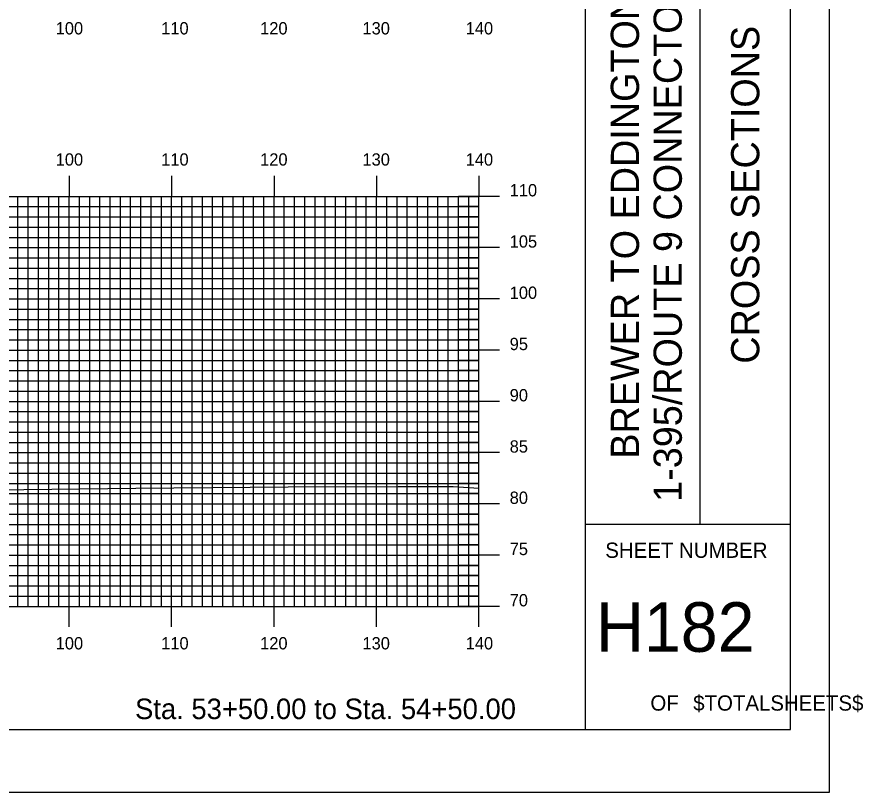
# Model space of a CAD drawing. Extents: x 1756282 to 1756625, y 442591 to 442811.
# Drawn here: x 1756542.5 to 1756625.1, y 442590.5 to 442666.2 of the extents above; entities that cross this region are included whole.
import ezdxf

# ---------------------------------------------------------------- set-up
doc = ezdxf.new("R2010")
doc.units = 0
for name, color, linetype in [('BORDER', 7, 'Continuous'), ('H_V ANNOTATION', 7, 'Continuous'), ('MAJOR', 7, 'Continuous'), ('MINOR', 7, 'Continuous'), ('PLOT BOUNDARY', 7, 'Continuous'), ('S_Roadway_Centerline', 7, 'Continuous')]:
    doc.layers.add(name, color=color, linetype=linetype)

msp = doc.modelspace()

# ---------------------------------------------------------------- linework, layer by layer
at = {"layer": 'BORDER'}
for p, q in [((1756597.97, 442596.665), (1756597.97, 442806.665)), ((1756609.152, 442616.671), (1756609.152, 442686.671)), ((1756597.97, 442616.671), (1756617.97, 442616.671))]:
    msp.add_line(p, q, dxfattribs=at)
msp.add_lwpolyline([(1756297.97, 442596.665), (1756617.97, 442596.665), (1756617.97, 442806.665), (1756297.97, 442806.665)], close=True, dxfattribs=at)
at = {"layer": 'MAJOR'}
for p, q in [((1756547.57, 442650.669), (1756547.57, 442648.665)), ((1756557.57, 442650.669), (1756557.57, 442648.665)), ((1756567.57, 442650.669), (1756567.57, 442648.665)), ((1756577.57, 442650.669), (1756577.57, 442648.665)), ((1756587.57, 442650.669), (1756587.57, 442648.665)), ((1756307.57, 442648.665), (1756587.57, 442648.665)), ((1756307.57, 442648.665), (1756587.57, 442648.665)), ((1756547.57, 442608.665), (1756547.57, 442648.665)), ((1756557.57, 442608.665), (1756557.57, 442648.665)), ((1756567.57, 442608.665), (1756567.57, 442648.665)), ((1756577.57, 442608.665), (1756577.57, 442648.665)), ((1756589.574, 442648.665), (1756585.566, 442648.665)), ((1756587.57, 442608.665), (1756587.57, 442648.665)), ((1756587.57, 442608.665), (1756587.57, 442648.665)), ((1756307.57, 442643.665), (1756587.57, 442643.665)), ((1756589.574, 442643.665), (1756585.566, 442643.665)), ((1756307.57, 442638.665), (1756587.57, 442638.665)), ((1756589.574, 442638.665), (1756585.566, 442638.665)), ((1756307.57, 442633.665), (1756587.57, 442633.665)), ((1756589.574, 442633.665), (1756585.566, 442633.665)), ((1756307.57, 442628.665), (1756587.57, 442628.665)), ((1756589.574, 442628.665), (1756585.566, 442628.665)), ((1756307.57, 442623.665), (1756587.57, 442623.665)), ((1756589.574, 442623.665), (1756585.566, 442623.665)), ((1756307.57, 442618.665), (1756587.57, 442618.665)), ((1756589.574, 442618.665), (1756585.566, 442618.665)), ((1756307.57, 442613.665), (1756587.57, 442613.665)), ((1756589.574, 442613.665), (1756585.566, 442613.665)), ((1756307.57, 442608.665), (1756587.57, 442608.665)), ((1756307.57, 442608.665), (1756587.57, 442608.665)), ((1756547.57, 442606.661), (1756547.57, 442608.665)), ((1756557.57, 442606.661), (1756557.57, 442608.665)), ((1756567.57, 442606.661), (1756567.57, 442608.665)), ((1756577.57, 442606.661), (1756577.57, 442608.665)), ((1756589.574, 442608.665), (1756585.566, 442608.665)), ((1756587.57, 442606.661), (1756587.57, 442608.665))]:
    msp.add_line(p, q, dxfattribs=at)
at = {"layer": 'MINOR'}
for p, q in [((1756542.57, 442608.665), (1756542.57, 442648.665)), ((1756543.57, 442608.665), (1756543.57, 442648.665)), ((1756544.57, 442608.665), (1756544.57, 442648.665)), ((1756545.57, 442608.665), (1756545.57, 442648.665)), ((1756546.57, 442608.665), (1756546.57, 442648.665)), ((1756548.57, 442608.665), (1756548.57, 442648.665)), ((1756549.57, 442608.665), (1756549.57, 442648.665)), ((1756550.57, 442608.665), (1756550.57, 442648.665)), ((1756551.57, 442608.665), (1756551.57, 442648.665)), ((1756552.57, 442608.665), (1756552.57, 442648.665)), ((1756553.57, 442608.665), (1756553.57, 442648.665)), ((1756554.57, 442608.665), (1756554.57, 442648.665)), ((1756555.57, 442608.665), (1756555.57, 442648.665)), ((1756556.57, 442608.665), (1756556.57, 442648.665)), ((1756558.57, 442608.665), (1756558.57, 442648.665)), ((1756559.57, 442608.665), (1756559.57, 442648.665)), ((1756560.57, 442608.665), (1756560.57, 442648.665)), ((1756561.57, 442608.665), (1756561.57, 442648.665)), ((1756562.57, 442608.665), (1756562.57, 442648.665)), ((1756563.57, 442608.665), (1756563.57, 442648.665)), ((1756564.57, 442608.665), (1756564.57, 442648.665)), ((1756565.57, 442608.665), (1756565.57, 442648.665)), ((1756566.57, 442608.665), (1756566.57, 442648.665)), ((1756568.57, 442608.665), (1756568.57, 442648.665)), ((1756569.57, 442608.665), (1756569.57, 442648.665)), ((1756570.57, 442608.665), (1756570.57, 442648.665)), ((1756571.57, 442608.665), (1756571.57, 442648.665)), ((1756572.57, 442608.665), (1756572.57, 442648.665)), ((1756573.57, 442608.665), (1756573.57, 442648.665)), ((1756574.57, 442608.665), (1756574.57, 442648.665)), ((1756575.57, 442608.665), (1756575.57, 442648.665)), ((1756576.57, 442608.665), (1756576.57, 442648.665)), ((1756578.57, 442608.665), (1756578.57, 442648.665)), ((1756579.57, 442608.665), (1756579.57, 442648.665)), ((1756580.57, 442608.665), (1756580.57, 442648.665)), ((1756581.57, 442608.665), (1756581.57, 442648.665)), ((1756582.57, 442608.665), (1756582.57, 442648.665)), ((1756583.57, 442608.665), (1756583.57, 442648.665)), ((1756584.57, 442608.665), (1756584.57, 442648.665)), ((1756585.57, 442608.665), (1756585.57, 442648.665)), ((1756586.57, 442608.665), (1756586.57, 442648.665)), ((1756307.57, 442647.665), (1756587.57, 442647.665)), ((1756587.57, 442647.665), (1756585.566, 442647.665)), ((1756307.57, 442646.665), (1756587.57, 442646.665)), ((1756587.57, 442646.665), (1756585.566, 442646.665)), ((1756307.57, 442645.665), (1756587.57, 442645.665)), ((1756587.57, 442645.665), (1756585.566, 442645.665)), ((1756307.57, 442644.665), (1756587.57, 442644.665)), ((1756587.57, 442644.665), (1756585.566, 442644.665)), ((1756307.57, 442642.665), (1756587.57, 442642.665)), ((1756587.57, 442642.665), (1756585.566, 442642.665)), ((1756307.57, 442641.665), (1756587.57, 442641.665)), ((1756587.57, 442641.665), (1756585.566, 442641.665)), ((1756307.57, 442640.665), (1756587.57, 442640.665)), ((1756587.57, 442640.665), (1756585.566, 442640.665)), ((1756307.57, 442639.665), (1756587.57, 442639.665)), ((1756587.57, 442639.665), (1756585.566, 442639.665)), ((1756307.57, 442637.665), (1756587.57, 442637.665)), ((1756587.57, 442637.665), (1756585.566, 442637.665)), ((1756307.57, 442636.665), (1756587.57, 442636.665)), ((1756587.57, 442636.665), (1756585.566, 442636.665)), ((1756307.57, 442635.665), (1756587.57, 442635.665)), ((1756587.57, 442635.665), (1756585.566, 442635.665)), ((1756307.57, 442634.665), (1756587.57, 442634.665)), ((1756587.57, 442634.665), (1756585.566, 442634.665)), ((1756307.57, 442632.665), (1756587.57, 442632.665)), ((1756587.57, 442632.665), (1756585.566, 442632.665)), ((1756307.57, 442631.665), (1756587.57, 442631.665)), ((1756587.57, 442631.665), (1756585.566, 442631.665)), ((1756307.57, 442630.665), (1756587.57, 442630.665)), ((1756587.57, 442630.665), (1756585.566, 442630.665)), ((1756307.57, 442629.665), (1756587.57, 442629.665)), ((1756587.57, 442629.665), (1756585.566, 442629.665)), ((1756307.57, 442627.665), (1756587.57, 442627.665)), ((1756587.57, 442627.665), (1756585.566, 442627.665)), ((1756307.57, 442626.665), (1756587.57, 442626.665)), ((1756587.57, 442626.665), (1756585.566, 442626.665)), ((1756307.57, 442625.665), (1756587.57, 442625.665)), ((1756587.57, 442625.665), (1756585.566, 442625.665)), ((1756307.57, 442624.665), (1756587.57, 442624.665)), ((1756587.57, 442624.665), (1756585.566, 442624.665)), ((1756307.57, 442622.665), (1756587.57, 442622.665)), ((1756587.57, 442622.665), (1756585.566, 442622.665)), ((1756307.57, 442621.665), (1756587.57, 442621.665)), ((1756587.57, 442621.665), (1756585.566, 442621.665)), ((1756307.57, 442620.665), (1756587.57, 442620.665)), ((1756587.57, 442620.665), (1756585.566, 442620.665)), ((1756307.57, 442619.665), (1756587.57, 442619.665)), ((1756587.57, 442619.665), (1756585.566, 442619.665)), ((1756307.57, 442617.665), (1756587.57, 442617.665)), ((1756587.57, 442617.665), (1756585.566, 442617.665)), ((1756307.57, 442616.665), (1756587.57, 442616.665)), ((1756587.57, 442616.665), (1756585.566, 442616.665)), ((1756307.57, 442615.665), (1756587.57, 442615.665)), ((1756587.57, 442615.665), (1756585.566, 442615.665)), ((1756307.57, 442614.665), (1756587.57, 442614.665)), ((1756587.57, 442614.665), (1756585.566, 442614.665)), ((1756307.57, 442612.665), (1756587.57, 442612.665)), ((1756587.57, 442612.665), (1756585.566, 442612.665)), ((1756307.57, 442611.665), (1756587.57, 442611.665)), ((1756587.57, 442611.665), (1756585.566, 442611.665)), ((1756307.57, 442610.665), (1756587.57, 442610.665)), ((1756587.57, 442610.665), (1756585.566, 442610.665)), ((1756307.57, 442609.665), (1756587.57, 442609.665)), ((1756587.57, 442609.665), (1756585.566, 442609.665))]:
    msp.add_line(p, q, dxfattribs=at)
at = {"layer": 'PLOT BOUNDARY'}
msp.add_lwpolyline([(1756281.783, 442590.547), (1756621.783, 442590.547), (1756621.783, 442810.547), (1756281.783, 442810.547)], close=True, dxfattribs=at)
at = {"layer": 'S_Roadway_Centerline'}
msp.add_lwpolyline([(1756307.57, 442618.076), (1756314.44, 442618.161), (1756314.669, 442617.912), (1756326.373, 442617.543), (1756331.277, 442617.486), (1756351.519, 442618.675), (1756360.562, 442619.108), (1756369.53, 442619.264), (1756401.492, 442619.32), (1756415.224, 442619.955), (1756421.47, 442620.052), (1756445.661, 442619.395), (1756471.396, 442619.404), (1756485.635, 442619.606), (1756486.605, 442619.72), (1756492.846, 442619.489), (1756514.562, 442620.043), (1756517.589, 442619.607), (1756534.909, 442619.984), (1756554.069, 442620.185), (1756568.955, 442620.313), (1756579.695, 442620.361), (1756585.039, 442620.349), (1756587.57, 442620.186)], dxfattribs=at)

# ---------------------------------------------------------------- texts
at = {"layer": 'BORDER'}
for s, p in [('1-395/ROUTE 9 CONNECTOR', (1756607.372, 442618.865)), ('BREWER TO EDDINGTON', (1756603.193, 442623.074)), ('CROSS SECTIONS', (1756614.939, 442632.339))]:
    msp.add_text(s, height=2.75575, rotation=90, dxfattribs=at).set_placement(p)
for s, height, p in [('SHEET NUMBER', 1.49054, (1756599.901, 442613.398)), ('H182', 4.8388, (1756599.001, 442604.23)), ('OF', 1.4905, (1756604.304, 442598.491)), ('$TOTALSHEETS$', 1.49054, (1756608.483, 442598.491))]:
    msp.add_text(s, height=height, dxfattribs=at).set_placement(p)
at = {"layer": 'H_V ANNOTATION'}
for s, height, p in [('100', 1.2, (1756546.253, 442664.465)), ('110', 1.2, (1756556.553, 442664.465)), ('120', 1.2, (1756566.21, 442664.465)), ('130', 1.2, (1756576.2, 442664.465)), ('140', 1.2, (1756586.275, 442664.465)), ('100', 1.2, (1756546.253, 442651.665)), ('110', 1.2, (1756556.553, 442651.665)), ('120', 1.2, (1756566.21, 442651.665)), ('130', 1.2, (1756576.2, 442651.665)), ('140', 1.2, (1756586.275, 442651.665)), ('110', 1.2, (1756590.57, 442648.665)), ('105', 1.2, (1756590.57, 442643.665)), ('100', 1.2, (1756590.57, 442638.665)), ('95', 1.2, (1756590.57, 442633.665)), ('90', 1.2, (1756590.57, 442628.665)), ('85', 1.2, (1756590.57, 442623.665)), ('80', 1.2, (1756590.57, 442618.665)), ('75', 1.2, (1756590.57, 442613.665)), ('70', 1.2, (1756590.57, 442608.665)), ('100', 1.2, (1756546.253, 442604.465)), ('110', 1.2, (1756556.553, 442604.465)), ('120', 1.2, (1756566.21, 442604.465)), ('130', 1.2, (1756576.2, 442604.465)), ('140', 1.2, (1756586.275, 442604.465)), ('Sta. 53+50.00 to Sta. 54+50.00', 2.0004, (1756554, 442597.665))]:
    msp.add_text(s, height=height, dxfattribs=at).set_placement(p)

doc.saveas('drawing.dxf')
